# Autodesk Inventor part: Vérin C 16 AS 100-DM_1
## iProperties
Shininess: 20.0
Angle Display Precision: 2
Document Length Units: 11269
Document Angle Units: 11279
Document Time Units: 11290
Document Mass Units: 11283
Document Length Units Precision: 3
Document Angle Units Precision: 2
Created: 2002-02
Part Number: Vérin C 16 AS 100-DM_1
Material: Par défaut
Document SubType Name: Modélisation
Designer: Administrateur
Density: 0.0
Volumn: 0.0
Area: 0.0
PropertySet Name: Model Information
Control State: 0
Master: False
Checked Out: False
Author: Administrateur
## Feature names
1. Base1
